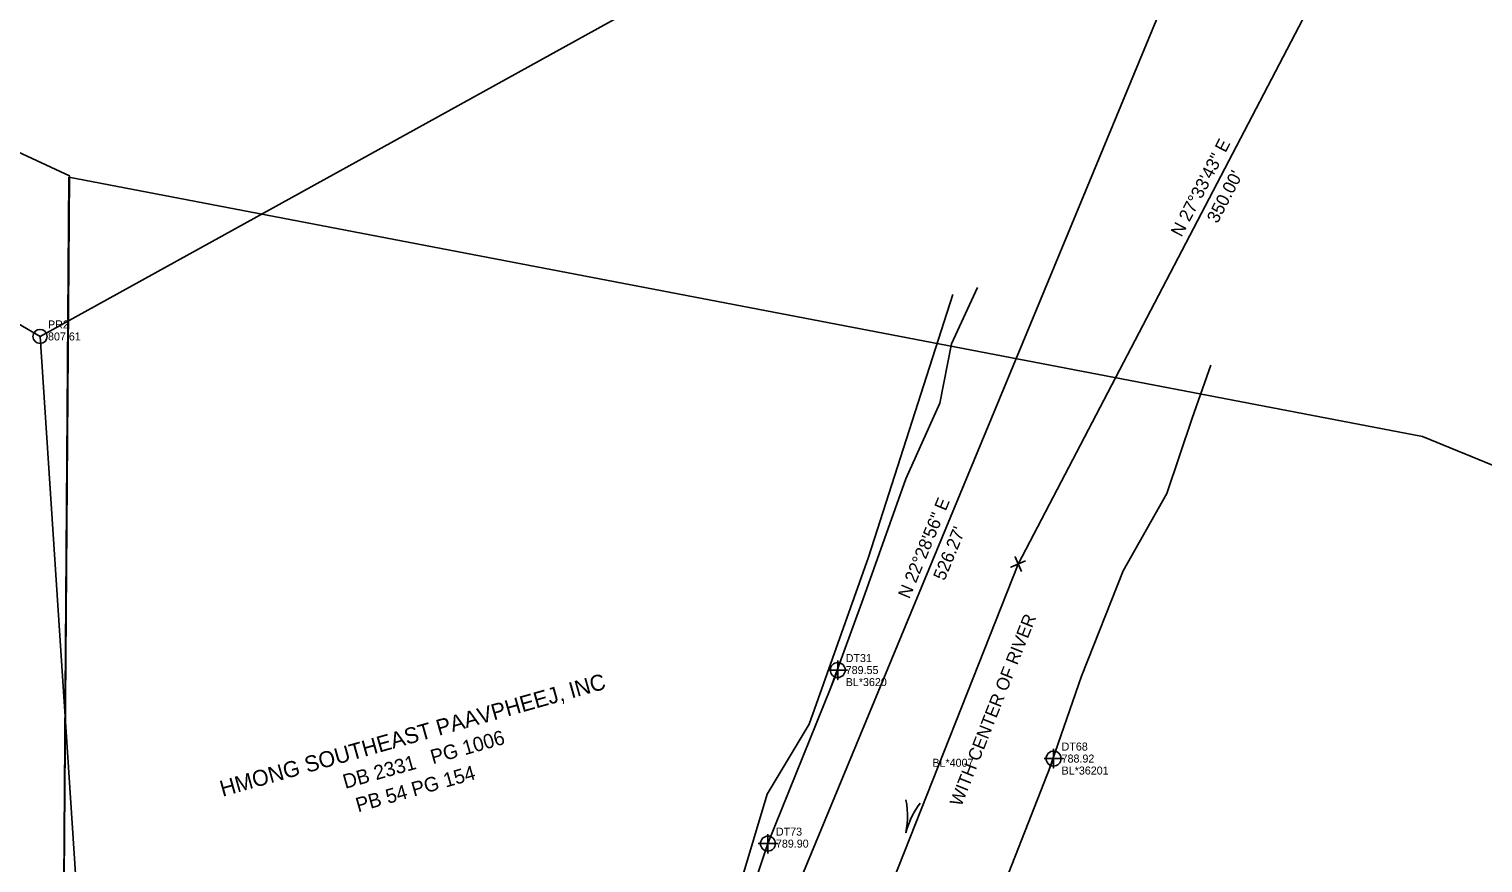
# Model space of a CAD drawing. Extents: x 1316460 to 1321645, y 684173 to 687077.
# Drawn here: x 1319422.2 to 1319876.5, y 686180.5 to 686441.2 of the extents above; entities that cross this region are included whole.
import ezdxf

# ---------------------------------------------------------------- set-up
doc = ezdxf.new("R2010")
doc.units = 0
for name, color, linetype in [('Exist DTM Breakline Underwater Cogo Comment', 7, 'Continuous'), ('Exist Hydro River Flow Arrow CELL', 7, 'Continuous'), ('Exist Hydro Stream Flow Arrow CELL', 7, 'Continuous'), ('Exist Hydro Stream or Body of Water Cogo Comment', 7, 'Continuous'), ('Exist Hydro Stream or Body of Water Cogo Elevation', 7, 'Continuous'), ('Exist Hydro Stream or Body of Water Cogo Number', 7, 'Continuous'), ('Exist Hydro Stream or Body of Water Cogo Point CELL', 7, 'Continuous'), ('Exist Hydrographic Confluence CELL', 7, 'Continuous'), ('Exist Hydrographic Confluence Cogo Elevation', 7, 'Continuous'), ('Exist Hydrographic Confluence Cogo Number', 7, 'Continuous'), ('Exist Hydrographic Water Edge Cogo Elevation', 7, 'Continuous'), ('Exist Property Corner CELL', 7, 'Continuous'), ('Exist Property Deed Book Text', 7, 'Continuous'), ('Exist Property Line', 7, 'Continuous'), ('Exist Property Line Text', 7, 'Continuous'), ('Exist Property Owner Text', 7, 'Continuous'), ('Exist Right of Way Easement Line', 7, 'Continuous'), ('Exist Vegetation Woods Line', 7, 'Continuous'), ('Old_Level_59', 7, 'Continuous')]:
    doc.layers.add(name, color=color, linetype=linetype)

# ---------------------------------------------------------------- blocks, each defined once
blk = doc.blocks.new('EXIST HYDRO STREAM FLOW ARROW')
at = {"layer": 'Exist Hydro Stream Flow Arrow CELL'}
blk.add_line((0, 0), (0, 0), dxfattribs=at)
for points in [[(-0.1, 0.04575), (-0.07325, 0.03375), (-0.04475, 0.0245), (-0.0165, 0.01575), (0.01175, 0.0095), (0.041, 0.00475), (0.07075, 0.0015), (0.1, 0)], [(-0.1, -0.04575), (-0.07325, -0.03375), (-0.04475, -0.0245), (-0.0165, -0.01575), (0.01175, -0.0095), (0.041, -0.00475), (0.07075, -0.0015), (0.1, 0)]]:
    blk.add_lwpolyline(points, dxfattribs=at)

msp = doc.modelspace()

# ---------------------------------------------------------------- linework, layer by layer
at = {"layer": 'Exist Hydro Stream or Body of Water Cogo Point CELL'}
for points in [[(1319671.85, 686240.81), (1319677.85, 686240.81), (1319674.85, 686240.81), (1319674.85, 686237.81), (1319674.85, 686243.81)], [(1319739.31, 686213.15), (1319745.31, 686213.15), (1319742.31, 686213.15), (1319742.31, 686210.15), (1319742.31, 686216.15)], [(1319650.04, 686186.56), (1319656.04, 686186.56), (1319653.04, 686186.56), (1319653.04, 686183.56), (1319653.04, 686189.56)]]:
    msp.add_lwpolyline(points, dxfattribs=at)
for centre in [(1319674.85, 686240.81), (1319742.31, 686213.15), (1319653.04, 686186.56)]:
    msp.add_circle(centre, 2.34, dxfattribs=at)
at = {"layer": 'Exist Hydrographic Confluence CELL'}
for radius in [2.2, 2.2, 0.0707, 0.0707]:
    msp.add_circle((1319425.58, 686345.09), radius, dxfattribs=at)
at = {"layer": 'Exist Hydrographic Water Edge Cogo Elevation'}
for points in [[(1319682.76, 686263.07), (1319696.09, 686300.55), (1319706.72, 686324.28), (1319710.37, 686342.76), (1319718.48, 686360.41)], [(1319751.05, 686238.9), (1319764.03, 686271.8), (1319777.7, 686295.98), (1319785.57, 686319.56), (1319791.41, 686336.08)], [(1319682.76, 686263.07), (1319672.67, 686235.39)], [(1319609.37, 686060.81), (1319617.66, 686076.4), (1319638.45, 686142.76), (1319653.04, 686186.56), (1319674.85, 686240.81)], [(1319751.05, 686238.9), (1319740.96, 686209.71)], [(1319671.78, 686037.22), (1319683.32, 686064.04), (1319703.85, 686108.2), (1319721.37, 686159.76), (1319742.31, 686213.15)]]:
    msp.add_lwpolyline(points, dxfattribs=at)
at = {"layer": 'Exist Property Corner CELL'}
msp.add_line((1319731.27, 686273.93), (1319731.27, 686273.93), dxfattribs=at)
msp.add_lwpolyline([(1319732.27, 686271.64), (1319730.28, 686276.23), (1319731.27, 686273.93), (1319728.98, 686272.94), (1319733.57, 686274.93)], dxfattribs=at)
at = {"layer": 'Exist Property Line'}
for p, q in [((1319731.27, 686273.93), (1319893.22, 686584.21)), ((1319623.43, 686079.33), (1319824.68, 686565.61)), ((1319811.35, 686558.24), (1319425.58, 686345.09)), ((1319425.58, 686345.09), (1319373.21, 686375.53)), ((1319650.35, 686069.59), (1319731.27, 686273.93))]:
    msp.add_line(p, q, dxfattribs=at)
at = {"layer": 'Exist Right of Way Easement Line'}
msp.add_lwpolyline([(1319425.58, 686345.09), (1319437.73, 686161.24)], dxfattribs=at)
at = {"layer": 'Exist Vegetation Woods Line'}
msp.add_lwpolyline([(1319710.84, 686358.17), (1319684.48, 686276.05), (1319665.93, 686223.9), (1319652.82, 686201.99), (1319635.98, 686145.96), (1319634.02, 686116.41), (1319613.48, 686083.15), (1319563.01, 686080.16)], dxfattribs=at)
at = {"layer": 'Old_Level_59'}
for points in [[(1318697.3, 685264.68), (1318675.61, 685496.37), (1319013.72, 685603.72), (1319178.5, 686302.95), (1319290.7, 686462.26), (1319434.76, 686395.34), (1319426.96, 685366.75), (1319230.41, 685144.48), (1318730.33, 685054.78)], [(1319434.63, 686394.86), (1319857.54, 686313.83), (1320008.45, 686252.06), (1320007, 685936.55), (1320002.29, 685545.5), (1319427.33, 685366.56)]]:
    msp.add_lwpolyline(points, close=True, dxfattribs=at)

# ---------------------------------------------------------------- block references
at = {"layer": 'Exist Hydro River Flow Arrow CELL', "xscale": 50, "yscale": 50, "rotation": -103.03931388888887}
msp.add_blockref('EXIST HYDRO STREAM FLOW ARROW', (1319697.26, 686194.82), dxfattribs=at)

# ---------------------------------------------------------------- texts
at = {"layer": 'Exist DTM Breakline Underwater Cogo Comment'}
msp.add_text('BL*4007', height=2.5, dxfattribs=at).set_placement((1319704.44, 686210.59))
at = {"layer": 'Exist Hydro Stream or Body of Water Cogo Comment'}
for s, p in [('BL*3620', (1319677.35, 686235.81)), ('BL*36201', (1319744.81, 686208.15))]:
    msp.add_text(s, height=2.5, dxfattribs=at).set_placement(p)
at = {"layer": 'Exist Hydro Stream or Body of Water Cogo Elevation'}
for s, p in [('789.55', (1319677.35, 686239.56)), ('788.92', (1319744.81, 686211.9)), ('789.90', (1319655.54, 686185.31))]:
    msp.add_text(s, height=2.5, dxfattribs=at).set_placement(p)
at = {"layer": 'Exist Hydro Stream or Body of Water Cogo Number'}
for s, p in [('DT31', (1319677.35, 686243.31)), ('DT68', (1319744.81, 686215.65)), ('DT73', (1319655.54, 686189.06))]:
    msp.add_text(s, height=2.5, dxfattribs=at).set_placement(p)
at = {"layer": 'Exist Hydrographic Confluence Cogo Elevation'}
msp.add_text('807.61', height=2.5, dxfattribs=at).set_placement((1319428.08, 686343.84))
msp.add_text('807.61', height=2.5, dxfattribs=at).set_placement((1319428.08, 686343.84))
at = {"layer": 'Exist Hydrographic Confluence Cogo Number'}
msp.add_text('PR2', height=2.5, dxfattribs=at).set_placement((1319428.08, 686347.59))
msp.add_text('PR2', height=2.5, dxfattribs=at).set_placement((1319428.08, 686347.59))
at = {"layer": 'Exist Property Deed Book Text'}
for s, p in [('DB 2331   PG 1006', (1319520.95, 686203.65)), ('PB 54 PG 154', (1319524.97, 686196.34))]:
    msp.add_text(s, height=4.5, rotation=15.7349, dxfattribs=at).set_placement(p)
at = {"layer": 'Exist Property Line Text'}
for s, rotation, p in [('N 27%%D33\'43" E', 62.438, (1319782.26, 686375.94)), ("350.00'", 62.438, (1319793.5, 686380.18)), ('N 22%%D28\'56" E', 67.5178, (1319697.22, 686262.85)), ("526.27'", 67.5178, (1319708.22, 686268.51)), ('WITH CENTER OF RIVER', 68.3949, (1319713.43, 686197.94))]:
    msp.add_text(s, height=4, rotation=rotation, dxfattribs=at).set_placement(p)
at = {"layer": 'Exist Property Owner Text'}
msp.add_text('HMONG SOUTHEAST PAAVPHEEJ, INC', height=5, rotation=15.7349, dxfattribs=at).set_placement((1319482.6, 686201.19))

doc.saveas('drawing.dxf')
